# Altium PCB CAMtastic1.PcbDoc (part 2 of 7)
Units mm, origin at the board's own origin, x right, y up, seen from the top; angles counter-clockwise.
Board outline 150.22 x 135.24 mm, 5 copper layers (Top Layer, Layer 1, Mid-Layer 1, Layer 2, Bottom Layer), stack 0.461 mm thick; 0 components, 362 nets, 2885 pads, 0 vias.
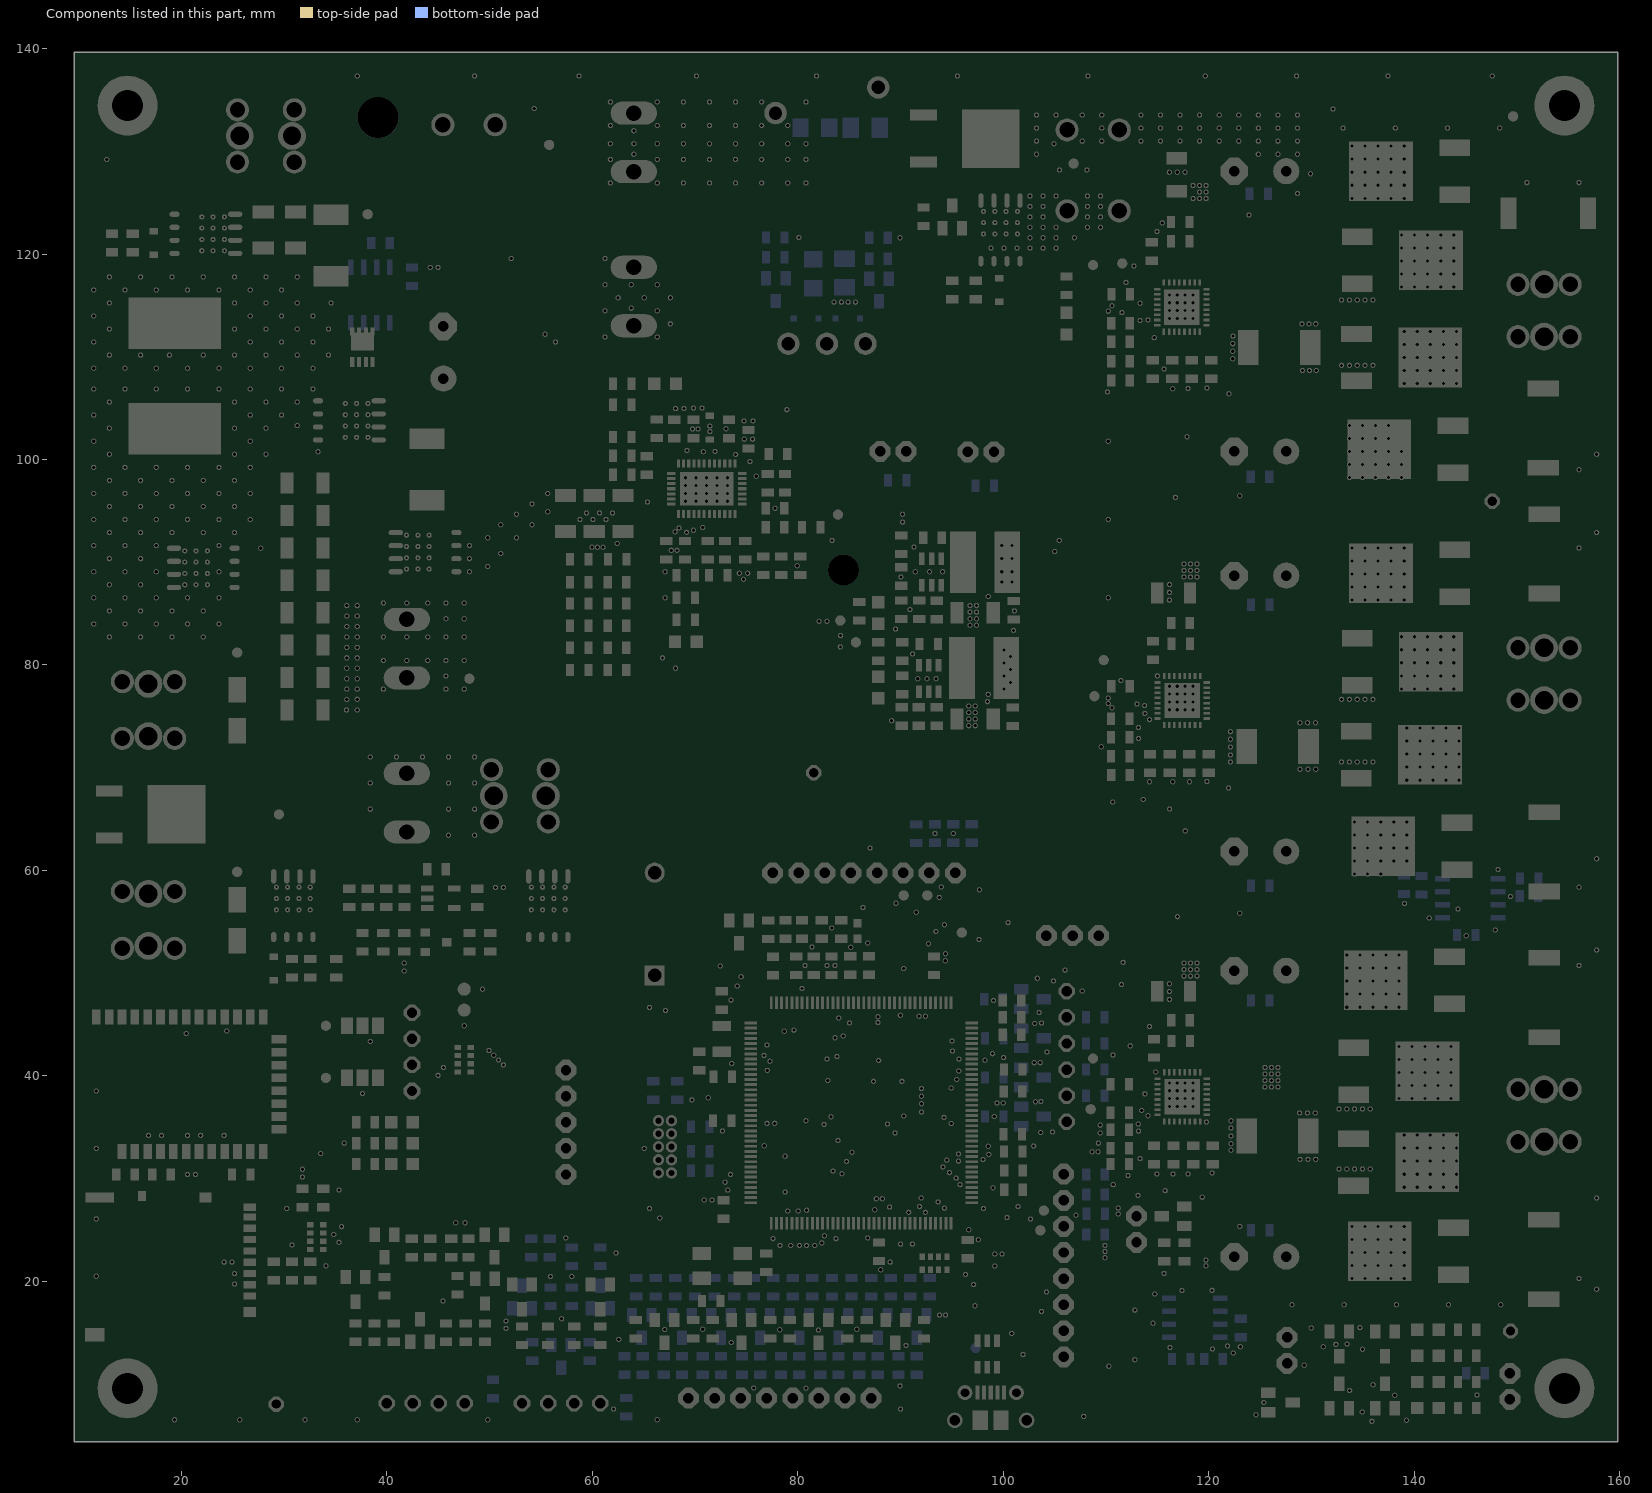
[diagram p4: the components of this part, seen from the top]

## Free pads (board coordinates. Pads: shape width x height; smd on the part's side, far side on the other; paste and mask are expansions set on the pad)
  round 0.508 hole 0.305 mask+0.61: 1(11.451,83.998) 1(11.451,86.538) 1(11.451,89.078) 1(11.451,91.618) 1(11.451,94.158) 1(11.451,96.698) 1(11.451,99.238) 1(11.451,101.778) 1(11.451,104.318) 1(11.451,106.858) 1(11.451,108.89) 1(11.451,111.43) 1(11.451,113.97) 1(11.451,116.51) 1(11.705,20.498) 1(11.705,26.086) 1(11.705,32.944) 1(11.705,38.532) 1(12.975,82.728) 1(12.975,85.268) 1(12.975,87.808) 1(12.975,90.348) 1(12.975,92.888) 1(12.975,95.428) 1(12.975,97.968) 1(12.975,100.508) 1(12.975,103.048) 1(12.975,105.588) 1(12.975,110.16) 1(12.975,112.7) 1(12.975,115.24) 1(12.975,117.78) 1(14.499,83.998) 1(14.499,86.538) 1(14.499,89.078) 1(14.499,91.618) 1(14.499,94.158) 1(14.499,96.698) 1(14.499,99.238) 1(14.499,106.858) 1(14.499,108.89) 1(14.499,116.51) 1(16.023,82.728) 1(16.023,85.268) 1(16.023,87.808) 1(16.023,90.348) 1(16.023,92.888) 1(16.023,95.428) 1(16.023,97.968) 1(16.023,110.16) 1(16.023,117.78) 1(16.785,34.214) 1(17.547,83.998) 1(17.547,86.538) 1(17.547,89.078) 1(17.547,91.618) 1(17.547,94.158) 1(17.547,96.698) 1(17.547,99.238) 1(17.547,106.858) 1(17.547,108.89) 1(17.547,116.51) 1(18.055,34.214) 1(18.817,110.16) 1(19.071,82.728) 1(19.071,85.268) 1(19.071,92.888) 1(19.071,95.428) 1(19.071,97.968) 1(19.071,117.78) 1(19.325,6.528) 1(20.455,44.12) 1(20.595,30.404) 1(20.595,34.214) 1(20.595,83.998) 1(20.595,86.538) 1(20.595,94.158) 1(20.595,96.698) 1(20.595,99.238) 1(20.595,106.858) 1(20.595,108.89) 1(20.595,116.51) 1(21.357,30.404) 1(21.865,34.214) 1(22.119,82.728) 1(22.119,85.268) 1(22.119,92.888) 1(22.119,95.428) 1(22.119,97.968) 1(22.119,110.16) 1(22.119,117.78) 1(23.643,83.998) 1(23.643,86.538) 1(23.643,89.078) 1(23.643,91.618) 1(23.643,94.158) 1(23.643,96.698) 1(23.643,99.238) 1(23.643,106.858) 1(23.643,108.89) 1(23.643,116.51) 1(24.151,21.868) 1(24.151,34.214) 1(24.405,44.374) 1(24.913,21.868) 1(25.167,19.736) 1(25.167,20.752) 1(25.167,92.888) 1(25.167,95.428) 1(25.167,97.968) 1(25.167,100.508) 1(25.167,103.048) 1(25.167,105.588) 1(25.167,110.16) 1(25.167,112.7) 1(25.167,115.24) 1(25.167,117.78) 1(25.675,6.528) 1(26.691,94.158) 1(26.691,96.698) 1(26.691,99.238) 1(26.691,101.778) 1(26.691,104.318) 1(26.691,106.858) 1(26.691,108.89) 1(26.691,111.43) 1(26.691,113.97) 1(26.691,116.51) 1(27.707,91.364) 1(28.215,100.508) 1(28.215,103.048) 1(28.215,105.588) 1(28.215,110.16) 1(28.215,112.7) 1(28.215,115.24) 1(28.215,117.78) 1(29.739,104.318) 1(29.739,106.858) 1(29.739,108.89) 1(29.739,111.43) 1(29.739,113.97) 1(29.739,116.51) 1(30.247,27.102) 1(30.755,23.546) 1(31.263,103.302) 1(31.263,105.588) 1(31.263,110.16) 1(31.263,112.7) 1(31.263,115.24) 1(31.263,117.78) 1(31.771,30.15) 1(31.771,30.912) 1(32.025,6.528) 1(32.787,106.858) 1(32.787,108.89) 1(32.787,111.43) 1(32.787,113.97) 1(33.295,100.762) 1(33.549,32.436) 1(34.057,21.514) 1(34.311,110.16) 1(34.311,112.7) 1(34.565,115.24) 1(34.819,24.562) 1(35.327,23.8) 1(35.327,28.88) 1(35.581,25.324) 1(35.835,33.452) 1(37.105,6.528) 1(37.105,137.338) 1(37.613,38.278) 1(38.375,43.358) 1(38.375,65.964) 1(38.375,68.504) 1(38.375,71.044) 1(39.645,77.648) 1(39.645,80.442) 1(39.645,82.728) 1(39.645,86.03) 1(40.915,71.044) 1(41.931,80.442) 1(41.931,82.728) 1(41.931,86.03) 1(43.455,71.044) 1(43.963,80.442) 1(43.963,82.728) 1(43.963,86.03) 1(44.217,118.702) 1(44.979,40.056) 1(44.979,118.702) 1(45.445,18.085) 1(45.487,40.818) 1(45.741,77.648) 1(45.741,78.918) 1(45.741,80.442) 1(45.741,82.728) 1(45.741,84.506) 1(45.741,86.03) 1(45.995,63.424) 1(45.995,65.964) 1(45.995,68.504) 1(45.995,71.044) 1(46.689,25.705) 1(47.519,44.882) 1(47.519,77.648) 1(47.519,80.442) 1(47.519,82.728) 1(47.519,84.506) 1(47.519,86.03) 1(47.604,25.705) 1(48.027,89.078) 1(48.027,90.348) 1(48.027,91.618) 1(48.535,63.424) 1(48.535,65.964) 1(48.535,68.504) 1(48.535,71.044) 1(48.535,137.338) 1(49.297,48.438) 1(49.805,6.528) 1(49.805,89.586) 1(49.805,92.38) 1(49.928,42.473) 1(50.395,42.006) 1(50.861,41.539) 1(51.075,90.856) 1(51.075,93.65) 1(51.329,41.072) 1(51.583,15.418) 1(51.591,16.129) 1(52.599,92.38) 1(52.599,94.666) 1(54.123,93.65) 1(54.123,95.682) 1(54.335,134.163) 1(55.393,112.192) 1(55.647,94.92) 1(55.647,96.698) 1(55.909,20.472) 1(56.409,111.43) 1(57.002,16.358) 1(57.408,24.232) 1(57.992,20.472) 1(58.695,137.338) 1(58.78,94.158) 1(59.415,94.793) 1(59.948,91.465) 1(60.05,94.158) 1(60.481,91.465) 1(60.685,94.793) 1(61.04,91.465) 1(61.235,111.938) 1(61.235,114.478) 1(61.235,117.018) 1(61.235,119.558) 1(61.32,94.158) 1(61.743,126.924) 1(61.743,129.21) 1(61.743,130.734) 1(61.743,132.512) 1(61.743,134.798) 1(61.955,94.793) 1(62.056,7.569) 1(62.31,22.758) 1(62.412,91.821) 1(62.505,115.748) 1(62.564,14.351) 1(63.775,114.732) 1(63.775,117.018) 1(64.029,129.718) 1(64.029,130.734) 1(64.029,132.004) 1(65.045,32.944) 1(65.045,115.748) 1(65.358,95.86) 1(65.553,27.102) 1(65.553,46.66) 1(66.315,6.528) 1(66.315,111.938) 1(66.315,114.478) 1(66.315,117.018) 1(66.315,126.924) 1(66.315,129.21) 1(66.315,130.734) 1(66.315,132.512) 1(66.315,134.798) 1(66.552,26.162) 1(66.823,80.696) 1(67.035,15.316) 1(67.077,86.538) 1(67.077,89.078) 1(67.111,46.355) 1(67.585,113.208) 1(67.585,115.748) 1(67.67,91.161) 1(68.051,92.964) 1(68.093,79.68) 1(68.101,104.953) 1(68.228,91.161) 1(68.432,93.345) 1(68.855,126.924) 1(68.855,129.21) 1(68.855,130.734) 1(68.855,132.512) 1(68.855,134.798) 1(68.914,104.978) 1(69.067,95.936) 1(69.067,96.698) 1(69.067,97.46) 1(69.067,98.222) 1(69.168,92.913) 1(69.194,100.889) 1(69.676,37.668) 1(69.752,102.972) 1(69.829,93.116) 1(69.829,105.004) 1(70.083,95.936) 1(70.083,96.698) 1(70.083,97.46) 1(70.083,98.222) 1(70.125,137.338) 1(70.286,102.972) 1(70.667,105.004) 1(70.743,15.342) 1(70.743,93.37) 1(70.794,100.762) 1(70.887,27.915) 1(71.099,95.936) 1(71.099,96.698) 1(71.099,97.46) 1(71.099,98.222) 1(71.276,37.871) 1(71.395,126.924) 1(71.395,129.21) 1(71.395,130.734) 1(71.395,132.512) 1(71.395,134.798) 1(71.429,102.718) 1(71.429,103.251) 1(71.645,27.915) 1(71.937,100.787) 1(72.115,95.936) 1(72.115,96.698) 1(72.115,97.46) 1(72.115,98.222) 1(72.445,50.698) 1(72.648,34.646) 1(72.919,29.642) 1(73.004,102.997) 1(73.131,95.936) 1(73.131,96.698) 1(73.131,97.46) 1(73.131,98.222) 1(73.173,28.88) 1(73.427,30.404) 1(73.486,47.371) 1(73.512,14.046) 1(73.562,41.199) 1(73.935,126.924) 1(73.935,129.21) 1(73.935,130.734) 1(73.935,132.512) 1(73.935,134.798) 1(73.943,100.482) 1(74.096,48.743) 1(74.299,88.925) 1(74.477,49.657) 1(74.705,88.341) 1(74.756,103.759) 1(74.782,101.981) 1(75.112,88.925) 1(75.34,99.797) 1(75.594,101.981) 1(75.62,103.759) 1(75.696,9.627) 1(75.95,98.374) 1(76.475,126.924) 1(76.475,129.21) 1(76.475,130.734) 1(76.475,132.512) 1(76.475,134.798) 1(76.712,41.986) 1(76.729,33.198) 1(76.991,43.002) 1(77.004,35.382) 1(77.017,40.538) 1(77.271,41.427) 1(77.576,24.155) 1(77.745,35.382) 1(77.779,95.25) 1(78.236,15.291) 1(78.261,23.495) 1(78.668,44.348) 1(78.761,28.694) 1(78.761,32.182) 1(78.922,104.851) 1(79.015,26.848) 1(79.015,126.924) 1(79.015,129.21) 1(79.015,130.734) 1(79.015,132.512) 1(79.303,23.495) 1(79.608,44.45) 1(79.938,89.662) 1(80.031,26.848) 1(80.09,121.615) 1(80.141,23.495) 1(80.395,48.514) 1(80.7,50.749) 1(80.776,9.601) 1(80.776,35.636) 1(80.793,126.924) 1(80.793,129.21) 1(80.793,130.734) 1(80.793,134.798) 1(80.852,23.495) 1(80.852,26.924) 1(81.36,52.553) 1(81.64,23.495) 1(81.809,137.338) 1(81.995,15.265) 1(82.063,84.252) 1(82.325,23.749) 1(82.554,35.281) 1(82.579,24.435) 1(82.825,84.252) 1(82.833,41.656) 1(82.833,50.749) 1(82.91,39.548) 1(83.214,36.017) 1(83.291,54.407) 1(83.333,92.126) 1(83.418,30.734) 1(83.519,115.316) 1(83.595,50.749) 1(83.621,43.713) 1(83.697,24.155) 1(83.799,41.885) 1(83.905,33.727) 1(83.976,45.644) 1(84.129,81.763) 1(84.154,82.855) 1(84.23,115.316) 1(84.281,30.48) 1(84.408,43.891) 1(84.738,31.674) 1(84.891,115.316) 1(85.018,45.161) 1(85.145,52.527) 1(85.272,32.563) 1(85.602,115.316) 1(85.729,15.342) 1(86.339,56.388) 1(86.796,24.232) 1(86.796,52.934) 1(87.024,62.179) 1(87.355,39.472) 1(87.482,26.975) 1(87.634,28.042) 1(87.786,45.199) 1(87.786,45.758) 1(87.863,41.504) 1(88.066,21.133) 1(88.218,28.042) 1(88.726,35.306) 1(88.929,27.229) 1(88.98,21.869) 1(89.128,74.574) 1(89.463,34.442) 1(89.514,83.49) 1(89.539,56.807) 1(89.937,121.59) 1(89.945,9.83) 1(89.971,45.898) 1(89.996,7.569) 1(89.996,23.622) 1(90.022,88.57) 1(90.123,39.472) 1(90.191,93.904) 1(90.191,94.666) 1(90.301,36.093) 1(90.301,50.444) 1(90.53,13.767) 1(90.784,26.721) 1(90.911,85.395) 1(91.139,23.622) 1(91.165,81.077) 1(91.292,91.491) 1(91.419,89.078) 1(91.52,55.931) 1(91.673,78.664) 1(91.8,45.809) 1(91.85,27.28) 1(92.003,28.118) 1(92.028,36.474) 1(92.028,37.287) 1(92.028,38.024) 1(92.028,38.76) 1(92.409,26.721) 1(92.409,45.809) 1(92.562,78.664) 1(92.714,52.857) 1(92.816,89.078) 1(93.349,63.602) 1(93.425,54.051) 1(93.451,78.664) 1(93.654,27.737) 1(93.755,57.379) 1(93.794,16.713) 1(93.959,58.395) 1(94.086,89.078) 1(94.111,31.14) 1(94.213,35.966) 1(94.263,27.127) 1(94.263,54.712) 1(94.34,51.206) 1(94.365,51.892) 1(94.378,16.713) 1(94.492,31.801) 1(94.746,30.582) 1(94.924,35.357) 1(94.924,38.811) 1(95,43.409) 1(95.051,42.418) 1(95.127,63.602) 1(95.406,30.048) 1(95.457,39.649) 1(95.525,137.338) 1(95.635,31.699) 1(95.635,32.41) 1(95.66,40.488) 1(95.686,41.631) 1(95.787,29.413) 1(96.321,20.676) 1(96.626,25.019) 1(96.626,74.092) 1(96.626,74.727) 1(96.626,75.362) 1(96.626,75.997) 1(96.753,83.871) 1(96.753,84.506) 1(96.753,85.141) 1(96.753,85.776) 1(97.108,19.685) 1(97.235,17.628) 1(97.261,74.092) 1(97.261,74.727) 1(97.261,75.362) 1(97.261,75.997) 1(97.388,83.871) 1(97.388,84.506) 1(97.388,85.141) 1(97.388,85.776) 1(97.565,24.054) 1(97.616,53.289) 1(97.667,58.115) 1(98.023,31.852) 1(98.065,27.102) 1(98.2,41.529) 1(98.454,76.429) 1(98.531,33.147) 1(98.531,77.14) 1(98.531,86.665) 1(98.581,32.36) 1(98.785,120.574) 1(98.937,42.164) 1(98.988,29.108) 1(99.039,47.346) 1(99.115,36.043) 1(99.166,21.488) 1(99.166,22.657) 1(99.382,37.363) 1(99.843,88.062) 1(99.843,89.078) 1(99.843,90.348) 1(99.843,91.618) 1(99.877,22.657) 1(99.991,37.363) 1(100.029,41.783) 1(100.055,77.648) 1(100.055,78.918) 1(100.055,80.188) 1(100.055,81.458) 1(100.055,120.574) 1(100.359,26.213) 1(100.461,54.915) 1(100.69,78.283) 1(100.69,79.553) 1(100.69,80.823) 1(100.817,14.935) 1(100.859,88.062) 1(100.859,89.078) 1(100.859,90.348) 1(100.859,91.618) 1(100.994,83.363) 1(101.071,85.268) 1(101.325,120.574) 1(101.426,27.28) 1(101.909,12.878) 1(102.595,120.574) 1(102.595,121.59) 1(102.595,122.606) 1(102.595,123.622) 1(102.595,124.638) 1(102.595,125.654) 1(102.645,26.06) 1(102.95,33.172) 1(103.001,41.288) 1(103.052,45.098) 1(103.128,37.478) 1(103.23,129.718) 1(103.23,130.988) 1(103.23,132.258) 1(103.23,133.528) 1(103.306,49.505) 1(103.484,46.177) 1(103.585,41.288) 1(103.636,34.493) 1(103.653,37.516) 1(103.711,45.14) 1(103.712,17.069) 1(103.865,120.574) 1(103.865,121.59) 1(103.865,122.606) 1(103.865,123.622) 1(103.865,124.638) 1(103.865,125.654) 1(104.195,18.974) 1(104.246,42.316) 1(104.779,34.544) 1(104.881,49.251) 1(104.923,130.734) 1(105.008,91.034) 1(105.135,120.574) 1(105.135,121.59) 1(105.135,122.606) 1(105.135,125.654) 1(105.135,133.528) 1(105.439,92.126) 1(105.465,128.194) 1(105.998,50.292) 1(106.913,121.59) 1(107.065,26.441) 1(107.675,48.26) 1(107.675,130.988) 1(107.675,133.528) 1(107.827,6.858) 1(108.132,128.194) 1(108.183,122.606) 1(108.183,123.622) 1(108.183,124.638) 1(108.183,125.654) 1(108.225,137.338) 1(108.64,32.614) 1(109.224,32.614) 1(109.249,33.452) 1(109.427,34.442) 1(109.427,35.204) 1(109.453,122.606) 1(109.453,123.622) 1(109.453,124.638) 1(109.453,125.654) 1(109.529,72.034) 1(109.58,130.988) 1(109.58,132.258) 1(109.58,133.528) 1(109.884,22.301) 1(109.884,22.911) 1(109.884,23.495) 1(110.138,106.578) 1(110.215,76.238) 1(110.215,76.772) 1(110.215,86.538) 1(110.215,94.158) 1(110.215,101.778) 1(110.215,114.44) 1(110.265,11.735) 1(110.57,75.832) 1(110.57,114.973) 1(110.646,66.65) 1(110.672,42.037) 1(110.697,29.413) 1(111.18,26.568) 1(111.18,27.127) 1(111.434,78.486) 1(111.485,48.895) 1(111.535,114.3) 1(111.662,51.054) 1(111.942,117.246) 1(112.145,30.302) 1(112.348,42.926) 1(112.704,118.834) 1(112.797,12.37) 1(112.797,17.196) 1(113.009,76.2) 1(113.11,28.372) 1(113.132,35.302) 1(113.161,34.62) 1(113.161,72.847) 1(113.161,73.914) 1(113.313,31.953) 1(113.313,113.538) 1(113.313,115.214) 1(113.39,130.988) 1(113.39,132.258) 1(113.39,133.528) 1(113.466,36.627) 1(113.618,66.904) 1(113.745,76.048) 1(113.771,38.252) 1(113.771,75.286) 1(114.075,36.119) 1(114.075,113.589) 1(114.228,44.806) 1(114.228,68.631) 1(114.228,74.676) 1(114.685,111.862) 1(114.736,18.771) 1(114.837,40.386) 1(114.939,30.455) 1(114.964,122.199) 1(114.99,78.943) 1(115.295,130.988) 1(115.295,132.258) 1(115.295,133.528) 1(115.472,123.038) 1(115.65,20.777) 1(115.65,108.814) 1(115.752,28.829) 1(116.158,37.033) 1(116.158,37.795) 1(116.158,38.557) 1(116.158,39.319) 1(116.158,47.447) 1(116.158,48.209) 1(116.158,48.971) 1(116.158,75.641) 1(116.158,76.403) 1(116.158,77.165) 1(116.158,77.927) 1(116.158,86.309) 1(116.158,87.071) 1(116.158,87.833) 1(116.158,113.741) 1(116.158,114.503) 1(116.158,115.265) 1(116.158,116.027) 1(116.158,127.965) 1(116.184,65.989) 1(116.209,13.564) 1(116.488,68.631) 1(116.488,106.883) 1(116.514,30.455) 1(116.742,96.317) 1(116.92,37.033) 1(116.92,37.795) 1(116.92,38.557) 1(116.92,39.319) 1(116.92,75.641) 1(116.92,76.403) 1(116.92,77.165) 1(116.92,77.927) 1(116.92,113.741) 1(116.92,114.503) 1(116.92,115.265) 1(116.92,116.027) 1(116.92,127.965) 1(116.946,55.499) 1(117.2,130.988) 1(117.2,132.258) 1(117.2,133.528) 1(117.377,19.101) 1(117.581,49.708) 1(117.581,50.343) 1(117.581,50.978) 1(117.581,88.57) 1(117.581,89.205) 1(117.581,89.84) 1(117.682,37.033) 1(117.682,37.795) 1(117.682,38.557) 1(117.682,39.319) 1(117.682,75.641) 1(117.682,76.403) 1(117.682,77.165) 1(117.682,77.927) 1(117.682,113.741) 1(117.682,114.503) 1(117.682,115.265) 1(117.682,116.027) 1(117.682,127.965) 1(117.708,63.856) 1(117.885,102.21) 1(117.987,30.455) 1(117.987,106.909) 1(118.114,68.631) 1(118.216,49.708) 1(118.216,50.343) 1(118.216,50.978) 1(118.216,88.57) 1(118.216,89.205) 1(118.216,89.84) 1(118.444,37.033) 1(118.444,37.795) 1(118.444,38.557) 1(118.444,39.319) 1(118.444,75.641) 1(118.444,76.403) 1(118.444,77.165) 1(118.444,77.927) 1(118.444,113.741) 1(118.444,114.503) 1(118.444,115.265) 1(118.444,116.027) 1(118.47,125.4) 1(118.47,126.67) 1(118.851,49.708) 1(118.851,50.343) 1(118.851,50.978) 1(118.851,88.57) 1(118.851,89.205) 1(118.851,89.84) 1(119.105,125.4) 1(119.105,126.035) 1(119.105,126.67) 1(119.105,130.988) 1(119.105,132.258) 1(119.105,133.528) 1(119.359,28.194) 1(119.655,137.338) 1(119.714,21.514) 1(119.714,22.073) 1(119.74,125.4) 1(119.74,126.035) 1(119.74,126.67) 1(119.765,35.509) 1(119.816,68.656) 1(119.816,106.959) 1(120.324,19.126) 1(120.324,30.556) 1(120.349,13.411) 1(121.01,130.988) 1(121.01,132.258) 1(121.01,133.528) 1(121.822,13.716) 1(121.924,68.021) 1(121.949,106.401) 1(122.102,70.561) 1(122.102,71.247) 1(122.102,72.009) 1(122.102,72.771) 1(122.102,73.508) 1(122.153,32.766) 1(122.153,33.401) 1(122.153,34.163) 1(122.153,34.925) 1(122.153,35.636) 1(122.328,109.804) 1(122.328,110.541) 1(122.328,111.277) 1(122.353,112.014) 1(122.381,13.03) 1(122.915,130.988) 1(122.915,132.258) 1(122.915,133.528) 1(123.016,25.349) 1(123.016,55.829) 1(123.016,96.469) 1(123.067,13.64) 1(123.905,123.8) 1(124.591,7.01) 1(124.82,129.718) 1(124.82,130.988) 1(124.82,132.258) 1(124.82,133.528) 1(125.353,8.204) 1(125.455,38.913) 1(125.455,39.548) 1(125.455,40.183) 1(125.455,40.818) 1(126.09,38.913) 1(126.09,39.548) 1(126.09,40.183) 1(126.09,40.818) 1(126.725,38.913) 1(126.725,39.548) 1(126.725,40.183) 1(126.725,40.818) 1(126.725,129.718) 1(126.725,130.988) 1(126.725,132.258) 1(126.725,133.528) 1(128.096,17.729) 1(128.545,137.338) 1(128.63,125.908) 1(128.63,129.718) 1(128.63,130.988) 1(128.63,132.258) 1(128.63,133.528) 1(128.833,36.398) 1(128.858,74.371) 1(128.884,31.877) 1(128.884,69.85) 1(129.061,113.208) 1(129.112,108.661) 1(129.29,11.836) 1(129.595,36.398) 1(129.62,74.371) 1(129.646,31.877) 1(129.646,69.85) 1(129.747,113.208) 1(129.798,108.661) 1(129.9,127.813) 1(129.976,15.469) 1(130.357,36.398) 1(130.382,74.371) 1(130.408,31.877) 1(130.408,69.85) 1(130.408,113.208) 1(130.458,108.661) 1(131.144,13.64) 1(132.084,134.112) 1(132.363,13.868) 1(132.668,30.937) 1(132.668,36.779) 1(132.922,70.561) 1(132.922,76.657) 1(132.922,109.169) 1(132.922,115.519) 1(133.075,132.258) 1(133.176,17.729) 1(133.43,30.937) 1(133.43,36.779) 1(133.43,46.685) 1(133.43,47.955) 1(133.43,49.225) 1(133.43,50.495) 1(133.43,51.765) 1(133.456,13.894) 1(133.684,70.561) 1(133.684,76.657) 1(133.684,98.247) 1(133.684,99.517) 1(133.684,100.787) 1(133.684,102.057) 1(133.684,103.327) 1(133.684,109.169) 1(133.684,115.519) 1(133.71,9.373) 1(133.938,20.269) 1(133.938,21.539) 1(133.938,22.809) 1(133.938,24.079) 1(133.938,25.349) 1(133.938,86.309) 1(133.938,87.579) 1(133.938,88.849) 1(133.938,90.119) 1(133.938,91.389) 1(133.938,125.425) 1(133.938,126.695) 1(133.938,127.965) 1(133.938,129.235) 1(133.938,130.505) 1(134.192,30.937) 1(134.192,36.779) 1(134.192,59.639) 1(134.192,60.909) 1(134.192,62.179) 1(134.192,63.449) 1(134.192,64.719) 1(134.446,70.561) 1(134.446,76.657) 1(134.446,109.169) 1(134.446,115.519) 1(134.7,15.494) 1(134.7,46.685) 1(134.7,47.955) 1(134.7,49.225) 1(134.7,50.495) 1(134.7,51.765) 1(134.929,7.29) 1(134.954,13.386) 1(134.954,30.937) 1(134.954,36.779) 1(134.954,98.247) 1(134.954,99.517) 1(134.954,100.787) 1(134.954,102.057) 1(134.954,103.327) 1(135.208,20.269) 1(135.208,21.539) 1(135.208,22.809) 1(135.208,24.079) 1(135.208,25.349) 1(135.208,70.561) 1(135.208,76.657) 1(135.208,86.309) 1(135.208,87.579) 1(135.208,88.849) 1(135.208,90.119) 1(135.208,91.389) 1(135.208,109.169) 1(135.208,115.519) 1(135.208,125.425) 1(135.208,126.695) 1(135.208,127.965) 1(135.208,129.235) 1(135.208,130.505) 1(135.462,59.639) 1(135.462,60.909) 1(135.462,62.179) 1(135.462,63.449) 1(135.462,64.719) 1(135.716,30.937) 1(135.716,36.779) 1(135.869,6.375) 1(135.97,46.685) 1(135.97,47.955) 1(135.97,49.225) 1(135.97,50.495) 1(135.97,51.765) 1(135.97,70.561) 1(135.97,76.657) 1(135.97,109.169) 1(135.97,115.519) 1(135.996,9.931) 1(136.224,98.247) 1(136.224,99.517) 1(136.224,100.787) 1(136.224,102.057) 1(136.224,103.327) 1(136.478,20.269) 1(136.478,21.539) 1(136.478,22.809) 1(136.478,24.079) 1(136.478,25.349) 1(136.478,86.309) 1(136.478,87.579) 1(136.478,88.849) 1(136.478,90.119) 1(136.478,91.389) 1(136.478,125.425) 1(136.478,126.695) 1(136.478,127.965) 1(136.478,129.235) 1(136.478,130.505) 1(136.732,59.639) 1(136.732,60.909) 1(136.732,62.179) 1(136.732,63.449) 1(136.732,64.719) 1(137.24,46.685) 1(137.24,47.955) 1(137.24,49.225) 1(137.24,50.495) 1(137.24,51.765) 1(137.435,137.338) 1(137.494,98.247) 1(137.494,99.517) 1(137.494,100.787) 1(137.494,102.057) 1(137.494,103.327) 1(137.748,20.269) 1(137.748,21.539) 1(137.748,22.809) 1(137.748,24.079) 1(137.748,25.349) 1(137.748,86.309) 1(137.748,87.579) 1(137.748,88.849) 1(137.748,90.119) 1(137.748,91.389) 1(137.748,125.425) 1(137.748,126.695) 1(137.748,127.965) 1(137.748,129.235) 1(137.748,130.505) 1(138.002,60.909) 1(138.002,62.179) 1(138.002,63.449) 1(138.002,64.719) 1(138.104,8.915) 1(138.155,132.258) 1(138.256,17.729) 1(138.51,37.795) 1(138.51,39.065) 1(138.51,40.335) 1(138.51,41.605) 1(138.51,42.875) 1(138.51,46.685) 1(138.51,47.955) 1(138.51,49.225) 1(138.51,50.495) 1(138.51,51.765) 1(138.764,77.673) 1(138.764,78.943) 1(138.764,80.213) 1(138.764,81.483) 1(138.764,82.753) 1(138.764,98.247) 1(138.764,99.517) 1(138.764,100.787) 1(138.764,116.789) 1(138.764,118.059) 1(138.764,119.329) 1(138.764,120.599) 1(138.764,121.869) 1(139.018,20.269) 1(139.018,21.539) 1(139.018,22.809) 1(139.018,24.079) 1(139.018,25.349) 1(139.018,29.159) 1(139.018,30.429) 1(139.018,31.699) 1(139.018,32.969) 1(139.018,34.239) 1(139.018,86.309) 1(139.018,87.579) 1(139.018,88.849) 1(139.018,90.119) 1(139.018,91.389) 1(139.018,107.391) 1(139.018,108.661) 1(139.018,109.931) 1(139.018,111.201) 1(139.018,112.471) 1(139.018,125.425) 1(139.018,126.695) 1(139.018,127.965) 1(139.018,129.235) 1(139.018,130.505) 1(139.046,56.769) 1(139.247,6.477) 1(139.272,60.909) 1(139.272,62.179) 1(139.272,63.449) 1(139.272,64.719) 1(139.272,68.783) 1(139.272,70.053) 1(139.272,71.323) 1(139.272,72.593) 1(139.272,73.863) 1(139.78,37.795) 1(139.78,39.065) 1(139.78,40.335) 1(139.78,41.605) 1(139.78,42.875) 1(140.034,77.673) 1(140.034,78.943) 1(140.034,80.213) 1(140.034,81.483) 1(140.034,82.753) 1(140.034,116.789) 1(140.034,118.059) 1(140.034,119.329) 1(140.034,120.599) 1(140.034,121.869) 1(140.288,29.159) 1(140.288,30.429) 1(140.288,31.699) 1(140.288,32.969) 1(140.288,34.239) 1(140.288,107.391) 1(140.288,108.661) 1(140.288,109.931) 1(140.288,111.201) 1(140.288,112.471) 1(140.542,68.783) 1(140.542,70.053) 1(140.542,71.323) 1(140.542,72.593) 1(140.542,73.863) 1(141.05,37.795) 1(141.05,39.065) 1(141.05,40.335) 1(141.05,41.605) 1(141.05,42.875) 1(141.304,77.673) 1(141.304,78.943) 1(141.304,80.213) 1(141.304,81.483) 1(141.304,82.753) 1(141.304,116.789) 1(141.304,118.059) 1(141.304,119.329) 1(141.304,120.599) 1(141.304,121.869) 1(141.459,55.372) 1(141.558,29.159) 1(141.558,30.429) 1(141.558,31.699) 1(141.558,32.969) 1(141.558,34.239) 1(141.558,107.391) 1(141.558,108.661) 1(141.558,111.201) 1(141.558,112.471) 1(141.812,68.783) 1(141.812,70.053) 1(141.812,71.323) 1(141.812,72.593) 1(141.812,73.863) 1(142.32,37.795) 1(142.32,39.065) 1(142.32,40.335) 1(142.32,41.605) 1(142.32,42.875) 1(142.574,77.673) 1(142.574,78.943) 1(142.574,80.213) 1(142.574,81.483) 1(142.574,82.753) 1(142.574,116.789) 1(142.574,118.059) 1(142.574,119.329) 1(142.574,120.599) 1(142.574,121.869) 1(142.828,29.159) 1(142.828,30.429) 1(142.828,31.699) 1(142.828,32.969) 1(142.828,34.239) 1(142.828,107.391) 1(142.828,108.661) 1(142.828,109.931) 1(142.828,111.201) 1(142.828,112.471) 1(143.082,68.783) 1(143.082,70.053) 1(143.082,71.323) 1(143.082,72.593) 1(143.082,73.863) 1(143.235,132.258) 1(143.336,17.729) 1(143.59,37.795) 1(143.59,39.065) 1(143.59,40.335) 1(143.59,41.605) 1(143.59,42.875) 1(143.844,77.673) 1(143.844,78.943) 1(143.844,80.213) 1(143.844,81.483) 1(143.844,82.753) 1(143.844,116.789) 1(143.844,118.059) 1(143.844,119.329) 1(143.844,120.599) 1(143.844,121.869) 1(144.098,29.159) 1(144.098,30.429) 1(144.098,31.699) 1(144.098,32.969) 1(144.098,34.239) 1(144.098,107.391) 1(144.098,108.661) 1(144.098,109.931) 1(144.098,111.201) 1(144.098,112.471) 1(144.251,56.236) 1(144.352,68.783) 1(144.352,70.053) 1(144.352,71.323) 1(144.352,72.593) 1(144.352,73.863) 1(145.063,53.645) 1(146.105,8.941) 1(147.595,137.338) 1(147.885,54.204) 1(148.162,60.096) 1(148.315,132.258) 1(148.416,17.729) 1(149.356,57.455) 1(150.956,126.949) 1(156.036,20.269) 1(156.036,50.749) 1(156.036,58.369) 1(156.036,91.389) 1(156.036,99.009) 1(156.036,126.949) 1(157.755,19.228) 1(157.755,28.118) 1(157.755,52.248) 1(157.755,61.138) 1(157.755,92.888) 1(157.755,100.508)
  rect 1.9x1.3 smd paste+0 mask+0.102: 1(11.542,14.818)
  rect 0.838x1.448 smd paste+0 mask+0.102: 1(11.692,45.738) 1(12.957,45.738) 1(14.206,32.631) 1(14.206,45.738) 1(15.456,32.631) 1(15.456,45.738) 1(16.706,32.631) 1(16.706,45.738) 1(17.956,32.631) 1(17.956,45.738) 1(19.205,32.631) 1(19.205,45.738) 1(20.455,32.631) 1(20.455,45.738) 1(21.705,32.631) 1(21.705,45.738) 1(22.954,32.631) 1(22.954,45.738) 1(24.204,32.631) 1(24.204,45.738) 1(25.454,32.631) 1(25.454,45.738) 1(26.703,32.631) 1(26.703,45.738) 1(27.953,32.631) 1(27.953,45.738)
  rect 2.8x1 smd paste+0 mask+0.102: 1(12.042,28.168)
  round 0.508 hole 0.305 mask+0.102: 1(12.721,129.21) 1(36.063,75.616) 1(36.089,76.632) 1(36.089,77.648) 1(36.089,78.664) 1(36.089,79.68) 1(36.089,80.696) 1(36.089,81.712) 1(36.089,82.728) 1(36.089,83.744) 1(36.089,84.76) 1(36.089,85.776) 1(37.105,75.616) 1(37.105,76.657) 1(37.105,77.648) 1(37.105,78.664) 1(37.105,79.68) 1(37.105,80.696) 1(37.105,81.712) 1(37.105,82.728) 1(37.105,83.744) 1(37.105,84.76) 1(37.105,85.776) 1(41.677,50.216) 1(41.677,50.978) 1(50.567,58.344) 1(51.329,58.344) 1(52.091,119.558) 1(114.575,15.926)
  rect 2.6x1.06 smd paste+0 mask+0.102: 1(12.975,63.17) 1(12.975,67.742) 1(92.223,128.956) 1(92.223,133.528)
  rect 1.2x0.8 smd paste+0 mask+0.102: 1(13.229,120.182) 1(13.229,121.982) 1(15.261,120.182) 1(15.261,121.982) 1(28.977,20.106) 1(28.977,21.906) 1(30.755,20.106) 1(30.755,21.906) 1(30.755,49.57) 1(30.755,51.37) 1(31.771,27.218) 1(31.771,29.018) 1(32.533,20.106) 1(32.533,21.906) 1(32.533,49.57) 1(32.533,51.37) 1(33.783,27.218) 1(33.783,29.018) 1(35.073,49.57) 1(35.073,51.37) 1(36.343,56.428) 1(36.343,58.228) 1(36.936,14.111) 1(36.936,15.911) 1(37.613,52.11) 1(37.613,53.91) 1(38.128,56.428) 1(38.128,58.228) 1(38.79,14.111) 1(38.79,15.911) 1(39.645,52.11) 1(39.645,53.91) 1(39.755,18.633) 1(39.755,20.433) 1(39.915,56.428) 1(39.915,58.228) 1(40.669,14.111) 1(40.669,15.911) 1(41.677,52.11) 1(41.677,53.91) 1(41.7,56.428) 1(41.7,58.228) 1(42.422,22.341) 1(42.422,24.141) 1(44.2,22.341) 1(44.2,24.141) 1(45.749,14.111) 1(45.749,15.911) 1(46.257,22.341) 1(46.257,24.141) 1(46.867,18.734) 1(46.867,20.534) 1(47.654,14.111) 1(47.654,15.911) 1(47.934,22.341) 1(47.934,24.141) 1(48.027,52.11) 1(48.027,53.91) 1(48.789,56.428) 1(48.789,58.228) 1(49.534,14.111) 1(49.534,15.911) 1(50.059,52.11) 1(50.059,53.91) 1(53.141,13.807) 1(53.141,15.607) 1(55.681,13.807) 1(55.681,15.607) 1(58.221,13.807) 1(58.221,15.607) 1(60.761,13.807) 1(60.761,15.607) 1(64.215,14.442) 1(64.215,16.242) 1(65.285,98.516) 1(65.285,100.316) 1(66.273,102.094) 1(66.273,103.894) 1(67.19,90.261) 1(67.19,92.061) 1(67.977,102.072) 1(67.977,103.872) 1(69.006,90.273) 1(69.006,92.073) 1(69.803,14.442) 1(69.803,16.242) 1(69.831,102.072) 1(69.831,103.872) 1(70.413,40.553) 1(70.413,42.353) 1(71.226,90.263) 1(71.226,92.063) 1(71.708,14.442) 1(71.708,16.242) 1(72.597,46.446) 1(72.597,48.246) 1(72.75,26.1) 1(72.75,27.9) 1(72.905,90.261) 1(72.905,92.061) 1(73.286,102.072) 1(73.286,103.872) 1(74.861,90.261) 1(74.861,92.061) 1(75.191,101.081) 1(75.191,102.881) 1(76.613,88.762) 1(76.613,90.562) 1(76.915,20.919) 1(76.915,22.719) 1(77.07,96.788) 1(77.07,98.588) 1(77.118,53.329) 1(77.118,55.129) 1(77.296,14.442) 1(77.296,16.242) 1(77.576,49.798) 1(77.576,51.598) 1(78.366,88.762) 1(78.366,90.562) 1(78.747,96.788) 1(78.747,98.588) 1(78.795,53.354) 1(78.795,55.154) 1(79.201,14.442) 1(79.201,16.242) 1(79.836,49.824) 1(79.836,51.624) 1(80.217,88.759) 1(80.217,90.559) 1(80.395,53.354) 1(80.395,55.154) 1(81.538,49.824) 1(81.538,51.624) 1(82.325,53.354) 1(82.325,55.154) 1(83.265,49.824) 1(83.265,51.624) 1(84.23,53.354) 1(84.23,55.154) 1(84.789,14.442) 1(84.789,16.242) 1(85.094,49.849) 1(85.094,51.649) 1(85.983,84.317) 1(85.983,86.117) 1(86.694,14.442) 1(86.694,16.242) 1(86.923,49.849) 1(86.923,51.649) 1(87.837,80.405) 1(87.837,82.205) 1(87.888,21.985) 1(87.888,23.785) 1(90.072,84.469) 1(90.072,86.269) 1(90.072,87.721) 1(90.072,89.521) 1(90.072,90.794) 1(90.072,92.594) 1(90.123,74.081) 1(90.123,75.881) 1(90.149,77.154) 1(90.149,78.954) 1(90.149,80.405) 1(90.149,82.205) 1(91.774,74.081) 1(91.774,75.881) 1(91.825,84.469) 1(91.825,86.269) 1(92.223,122.722) 1(92.223,124.522) 1(92.282,14.442) 1(92.282,16.242) 1(93.247,49.824) 1(93.247,51.624) 1(93.501,74.081) 1(93.501,75.881) 1(93.501,84.444) 1(93.501,86.244) 1(95.017,115.61) 1(95.017,117.41) 1(96.524,22.239) 1(96.524,24.039) 1(97.303,115.61) 1(97.303,117.41) 1(100.918,74.055) 1(100.918,75.855) 1(101.02,84.419) 1(101.02,86.219) 1(106.151,116.016) 1(106.151,117.816) 1(114.279,69.509) 1(114.279,71.309) 1(114.459,119.344) 1(114.459,121.144) 1(114.533,107.863) 1(114.533,109.663) 1(114.561,80.519) 1(114.561,82.319) 1(114.66,31.409) 1(114.66,33.209) 1(114.662,41.778) 1(114.662,43.578) 1(115.65,21.96) 1(115.65,23.76) 1(116.184,69.509) 1(116.184,71.309) 1(116.438,107.863) 1(116.438,109.663) 1(116.565,31.409) 1(116.565,33.209) 1(117.631,21.96) 1(117.631,23.76) 1(118.089,69.509) 1(118.089,71.309) 1(118.343,107.863) 1(118.343,109.663) 1(118.47,31.409) 1(118.47,33.209) 1(119.994,69.509) 1(119.994,71.309) 1(120.248,107.863) 1(120.248,109.663) 1(120.375,31.409) 1(120.375,33.209)
  rect 0.8x1.2 smd paste+0 mask+0.102: 1(13.637,30.404) 1(15.437,30.404) 1(17.155,30.404) 1(18.954,30.404) 1(24.922,30.404) 1(26.722,30.404) 1(37.001,31.42) 1(37.001,33.452) 1(37.001,35.484) 1(38.801,31.42) 1(38.801,33.452) 1(38.801,35.484) 1(43.927,60.122) 1(45.726,60.122) 1(57.81,79.509) 1(57.81,81.668) 1(57.81,83.827) 1(57.81,85.986) 1(57.81,88.044) 1(57.81,90.304) 1(59.609,79.509) 1(59.609,81.668) 1(59.609,83.827) 1(59.609,85.986) 1(59.609,88.044) 1(59.609,90.304) 1(61.493,79.509) 1(61.493,81.668) 1(61.493,83.827) 1(61.493,85.986) 1(61.493,88.044) 1(61.518,90.304) 1(61.997,98.527) 1(61.997,100.355) 1(61.997,102.184) 1(61.997,105.334) 1(61.997,107.366) 1(63.292,79.509) 1(63.292,81.668) 1(63.292,83.827) 1(63.292,85.986) 1(63.292,88.044) 1(63.318,90.304) 1(63.797,98.527) 1(63.797,100.355) 1(63.797,102.184) 1(63.797,105.334) 1(63.797,107.366) 1(68.192,84.416) 1(68.192,86.538) 1(68.192,88.722) 1(69.992,84.416) 1(69.992,86.538) 1(69.992,88.722) 1(70.656,18.085) 1(71.345,88.748) 1(71.748,35.636) 1(71.774,39.929) 1(72.456,18.085) 1(73.144,88.748) 1(73.548,35.636) 1(73.573,39.929) 1(76.879,93.396) 1(76.879,95.247) 1(77.158,100.536) 1(78.679,93.396) 1(78.679,95.247) 1(78.958,100.536) 1(80.401,93.396) 1(82.2,93.396) 1(91.84,82.042) 1(92.195,92.38) 1(93.639,82.042) 1(93.995,92.38) 1(99.942,44.018) 1(99.942,45.695) 1(99.942,47.346) 1(100.018,34.315) 1(100.044,38.481) 1(100.063,32.643) 1(100.069,40.615) 1(100.088,28.91) 1(100.088,30.789) 1(101.742,44.018) 1(101.742,45.695) 1(101.742,47.346) 1(101.818,34.315) 1(101.844,38.481) 1(101.863,32.643) 1(101.869,40.615) 1(101.888,28.91) 1(101.888,30.789) 1(110.43,31.42) 1(110.435,32.969) 1(110.435,34.773) 1(110.435,36.398) 1(110.435,39.198) 1(110.486,71.12) 1(110.486,72.974) 1(110.486,74.752) 1(110.506,69.291) 1(110.511,77.914) 1(110.511,107.696) 1(110.511,109.55) 1(110.511,111.455) 1(110.511,113.259) 1(110.536,116.078) 1(112.23,31.42) 1(112.235,32.969) 1(112.235,34.773) 1(112.235,36.398) 1(112.235,39.198) 1(112.286,71.12) 1(112.286,72.974) 1(112.286,74.752) 1(112.306,69.291) 1(112.311,77.914) 1(112.311,107.696) 1(112.311,109.55) 1(112.311,111.455) 1(112.311,113.259) 1(112.336,116.078) 1(116.328,121.234) 1(116.328,123.114) 1(116.353,45.421) 1(116.353,84.086) 1(116.378,43.389) 1(116.378,82.08) 1(118.128,121.234) 1(118.128,123.114) 1(118.153,45.421) 1(118.153,84.086) 1(118.178,43.389) 1(118.178,82.08) 1(144.242,7.671) 1(144.242,10.211) 1(144.242,12.751) 1(144.242,15.291) 1(146.042,7.671) 1(146.042,10.211) 1(146.042,12.751) 1(146.042,15.291)
  round 2.25 hole 1.5 mask+0.102: 1(14.245,52.421) 1(14.245,57.951) 1(14.245,72.851) 1(14.245,78.381) 1(19.325,52.421) 1(19.325,57.951) 1(19.325,72.851) 1(19.325,78.381) 1(25.45,128.956) 1(25.45,134.036) 1(30.98,128.956) 1(30.98,134.036) 1(45.445,132.588) 1(50.17,64.718) 1(50.17,69.798) 1(50.525,132.588) 1(55.7,64.718) 1(55.7,69.798) 1(106.201,124.206) 1(106.201,132.08) 1(111.281,124.206) 1(111.281,132.08) 1(150.093,33.604) 1(150.093,38.684) 1(150.093,76.581) 1(150.093,81.661) 1(150.093,111.963) 1(150.093,117.043) 1(155.173,33.604) 1(155.173,38.684) 1(155.173,76.581) 1(155.173,81.661) 1(155.173,111.963) 1(155.173,117.043)
  round 5.842 hole 3 mask+0.102: 1(14.753,9.576) 1(14.753,134.451) 1(154.613,9.576) 1(154.613,134.451)
  rect 0.8x1 smd paste+0 mask+0.102: 1(16.141,28.318)
  round 2.7 hole 1.8 mask+0.102: 1(16.785,52.646) 1(16.785,57.726) 1(16.785,73.076) 1(16.785,78.156) 1(25.675,131.496) 1(30.755,131.496) 1(50.395,67.258) 1(55.475,67.258) 1(152.633,33.604) 1(152.633,38.684) 1(152.633,76.581) 1(152.633,81.661) 1(152.633,111.963) 1(152.633,117.043)
  rect 0.83x0.63 smd paste+0 mask+0.102: 1(17.293,119.932) 1(17.293,122.232) 1(28.977,49.32) 1(28.977,51.62) 1(71.432,101.948) 1(71.432,104.249) 1(99.589,115.36) 1(99.589,117.66)
  oval 1.4x0.5 smd paste+0 mask+0.102: 1(19.267,87.554) 1(19.267,88.824) 1(19.267,90.094) 1(19.267,91.364) 1(25.222,120.066) 1(25.222,121.336) 1(25.222,122.606) 1(25.222,123.876) 1(39.193,101.905) 1(39.193,103.175) 1(39.193,104.445) 1(39.193,105.715) 1(40.857,89.078) 1(40.857,90.348) 1(40.857,91.618) 1(40.857,92.888)
  oval 1x0.5 smd paste+0 mask+0.102: 1(19.323,120.066) 1(19.323,121.336) 1(19.323,122.606) 1(19.323,123.876) 1(25.167,87.554) 1(25.167,88.824) 1(25.167,90.094) 1(25.167,91.364) 1(33.293,101.905) 1(33.293,103.175) 1(33.293,104.445) 1(33.293,105.715) 1(46.757,89.078) 1(46.757,90.348) 1(46.757,91.618) 1(46.757,92.888)
  rect 9x5 smd paste+0 mask+0.102: 1(19.325,102.978) 1(19.325,113.278)
  rect 5.632x5.7 smd paste+0 mask+0.102: 1(19.524,65.456) 1(98.772,131.242)
  round 0.5 hole 0.2 mask+0.102: 1(20.317,87.809) 1(20.317,88.909) 1(20.317,90.009) 1(20.317,91.109) 1(21.417,87.809) 1(21.417,88.909) 1(21.417,90.009) 1(21.417,91.109) 1(21.973,120.321) 1(21.973,121.421) 1(21.973,122.521) 1(21.973,123.621) 1(22.517,87.809) 1(22.517,88.909) 1(22.517,90.009) 1(22.517,91.109) 1(23.073,120.321) 1(23.073,121.421) 1(23.073,122.521) 1(23.073,123.621) 1(24.173,120.321) 1(24.173,121.421) 1(24.173,122.521) 1(24.173,123.621) 1(29.232,56.168) 1(29.232,57.268) 1(29.232,58.368) 1(30.332,56.168) 1(30.332,57.268) 1(30.332,58.368) 1(31.431,56.168) 1(31.431,57.268) 1(31.431,58.368) 1(32.532,56.168) 1(32.532,57.268) 1(32.532,58.368) 1(35.943,102.16) 1(35.943,103.26) 1(35.943,104.36) 1(35.943,105.46) 1(37.043,102.16) 1(37.043,103.26) 1(37.043,104.36) 1(37.043,105.46) 1(38.143,102.16) 1(38.143,103.26) 1(38.143,104.36) 1(38.143,105.46) 1(41.907,89.333) 1(41.907,90.433) 1(41.907,91.533) 1(41.907,92.633) 1(43.007,89.333) 1(43.007,90.433) 1(43.007,91.533) 1(43.007,92.633) 1(44.107,89.333) 1(44.107,90.433) 1(44.107,91.533) 1(44.107,92.633) 1(54.05,56.168) 1(54.05,57.268) 1(54.05,58.368) 1(55.149,56.168) 1(55.149,57.268) 1(55.149,58.368) 1(56.25,56.168) 1(56.25,57.268) 1(56.25,58.368) 1(57.35,56.168) 1(57.35,57.268) 1(57.35,58.368) 1(98.066,121.954) 1(98.066,123.054) 1(98.066,124.154) 1(99.166,121.954) 1(99.166,123.054) 1(99.166,124.154) 1(100.265,121.954) 1(100.265,123.054) 1(100.265,124.154) 1(101.366,121.954) 1(101.366,123.054) 1(101.366,124.154)
  rect 1.2x1 smd paste+0 mask+0.102: 1(22.342,28.168) 1(26.642,17.018)
  rect 1.7x2.5 smd paste+0 mask+0.102: 1(25.421,53.152) 1(25.421,57.152) 1(25.421,73.582) 1(25.421,77.582)
  rrect100% 1x1 smd paste+0 mask+0.102: 1(25.421,59.868) 1(25.421,81.204) 1(29.485,65.456) 1(34.057,39.802) 1(34.057,44.882) 1(38.121,123.876) 1(48.027,78.664) 1(84.129,84.328) 1(85.653,82.207) 1(90.301,57.569) 1(92.6,57.569) 1(103.598,24.968) 1(103.941,26.886) 1(106.839,128.803) 1(108.5,36.754) 1(108.729,41.694) 1(108.729,118.923) 1(108.868,76.962) 1(109.77,80.48) 1(111.574,119.088)
  rect 1.2x0.7 smd paste+0 mask+0.102: 1(26.642,18.568) 1(26.642,19.668) 1(26.642,20.768) 1(26.642,21.868) 1(26.642,22.968) 1(26.642,24.068) 1(26.642,25.168) 1(26.642,26.268) 1(26.642,27.218)
  rect 2.06x1.27 smd paste+0 mask+0.102: 1(27.961,120.597) 1(27.961,124.107) 1(31.101,120.597) 1(31.101,124.107) 1(57.383,92.987) 1(57.383,96.497) 1(60.177,92.987) 1(60.177,96.497) 1(62.971,92.987) 1(62.971,96.497)
  oval 0.5x1 smd paste+0 mask+0.102: 1(28.977,53.518) 1(30.247,53.518) 1(31.517,53.518) 1(32.787,53.518) 1(53.795,53.518) 1(55.065,53.518) 1(56.335,53.518) 1(57.605,53.518) 1(97.811,119.304) 1(99.081,119.304) 1(100.351,119.304) 1(101.621,119.304)
  oval 0.5x1.4 smd paste+0 mask+0.102: 1(28.977,59.418) 1(30.247,59.418) 1(31.517,59.418) 1(32.787,59.418) 1(53.795,59.418) 1(55.065,59.418) 1(56.335,59.418) 1(57.605,59.418) 1(97.811,125.204) 1(99.081,125.204) 1(100.351,125.204) 1(101.621,125.204)
  oct 1.408x1.408 / inner round 1.301 / far side oct 1.408x1.408 hole 0.9 rot 45 mask+0.102: 1(29.231,8.052) 1(81.555,69.52) 1(147.595,95.936) 1(149.373,15.164)
  rect 1.448x0.838 smd paste+0 mask+0.102: 1(29.485,34.803) 1(29.485,36.053) 1(29.485,37.302) 1(29.485,38.552) 1(29.485,39.802) 1(29.485,41.051) 1(29.485,42.301) 1(29.485,43.566)
  rect 1.27x2.06 smd paste+0 mask+0.102: 1(30.27,75.616) 1(30.27,78.773) 1(30.27,81.929) 1(30.27,85.086) 1(30.27,88.243) 1(30.27,91.4) 1(30.27,94.557) 1(30.27,97.714) 1(33.779,75.616) 1(33.779,78.773) 1(33.779,81.929) 1(33.779,85.086) 1(33.779,88.243) 1(33.779,91.4) 1(33.779,94.557) 1(33.779,97.714) 1(95.506,74.727) 1(95.506,85.09) 1(99.016,74.727) 1(99.016,85.09)
  rect 0.65x0.5 smd paste+0 mask+0.102: 1(32.533,23.108) 1(32.533,23.908) 1(32.533,24.708) 1(32.533,25.508) 1(33.783,23.108) 1(33.783,23.908) 1(33.783,24.708) 1(33.783,25.508) 1(46.893,40.38) 1(46.893,41.18) 1(46.893,41.98) 1(46.893,42.78) 1(48.144,40.38) 1(48.144,41.18) 1(48.144,41.98) 1(48.144,42.78)
  rect 3.4x2 smd paste+0 mask+0.102: 1(34.565,117.828) 1(34.565,123.828) 1(43.906,96.032) 1(43.906,102.032)
  rect 1x1.4 smd paste+0 mask+0.102: 1(35.986,20.428) 1(36.936,18.028) 1(37.886,20.428) 1(38.805,24.544) 1(39.755,22.344) 1(40.705,24.544) 1(42.26,14.115) 1(43.209,16.315) 1(44.159,14.115) 1(48.584,20.25) 1(49.524,24.544) 1(49.534,17.85) 1(50.474,22.344) 1(50.484,20.25) 1(51.424,24.544) 1(52.191,19.691) 1(53.141,17.291) 1(54.091,19.691) 1(59.811,19.691) 1(60.761,17.291) 1(61.711,19.691) 1(66.059,16.238) 1(67.009,14.038) 1(67.959,16.238) 1(73.324,55.126) 1(73.552,16.238) 1(74.274,52.926) 1(74.502,14.038) 1(75.224,55.126) 1(75.452,16.238) 1(81.045,16.238) 1(81.995,14.038) 1(82.945,16.238) 1(88.538,16.238) 1(89.488,14.038) 1(90.438,16.238) 1(94.067,122.522) 1(95.017,124.722) 1(95.967,122.522) 1(131.746,7.639) 1(131.746,15.119) 1(132.696,10.039) 1(132.696,12.719) 1(133.646,7.639) 1(133.646,15.119) 1(136.191,7.639) 1(136.191,15.119) 1(137.141,10.039) 1(137.141,12.719) 1(138.091,7.639) 1(138.091,15.119)
  rect 1.168x1.6 smd paste+0 mask+0.102: 1(36.089,39.802) 1(36.089,44.882) 1(37.613,39.802) 1(37.613,44.882) 1(39.137,39.802) 1(39.137,44.882)
  rect 0.55x1.5 smd far side paste+0 mask+0.102: 1(36.47,113.302) 1(36.47,118.702) 1(37.74,113.302) 1(37.74,118.702) 1(39.01,113.302) 1(39.01,118.702) 1(40.28,113.302) 1(40.28,118.702)
  rect 0.405x0.99 smd paste+0 mask+0.102: 1(36.622,109.487) 1(37.283,109.487) 1(37.943,109.487) 1(38.603,109.487)
  rect 0.405x0.76 smd paste+0 mask+0.102: 1(36.622,112.472) 1(37.283,112.472) 1(37.943,112.472) 1(38.603,112.472)
  rect 2.235x1.725 smd paste+0 mask+0.102: 1(37.613,111.479)
  rect 0.8x1.2 smd far side paste+0 mask+0.102: 1(38.48,121.082) 1(40.28,121.082) 1(69.589,30.759) 1(69.589,32.664) 1(69.589,35.052) 1(71.389,30.759) 1(71.389,32.664) 1(71.389,35.052) 1(76.905,119.705) 1(76.905,121.61) 1(78.705,119.705) 1(78.705,121.61) 1(86.955,119.558) 1(86.955,121.59) 1(88.754,119.558) 1(88.754,121.59) 1(88.783,97.968) 1(90.582,97.968) 1(97.289,97.46) 1(98.139,47.473) 1(98.215,36.043) 1(98.215,39.853) 1(98.215,43.663) 1(99.088,97.46) 1(99.939,47.473) 1(100.015,36.043) 1(100.015,39.853) 1(100.015,43.663) 1(108.045,38.075) 1(108.045,40.615) 1(108.045,43.155) 1(108.045,45.695) 1(108.073,24.562) 1(108.073,28.448) 1(108.073,30.404) 1(108.098,26.568) 1(109.845,38.075) 1(109.845,40.615) 1(109.845,43.155) 1(109.845,45.695) 1(109.873,24.562) 1(109.873,28.448) 1(109.873,30.404) 1(109.898,26.568) 1(116.404,12.446) 1(118.204,12.446) 1(119.553,12.446) 1(121.353,12.446) 1(123.971,125.882) 1(124.072,98.323) 1(124.098,24.968) 1(124.098,47.346) 1(124.098,58.496) 1(124.098,85.877) 1(125.77,125.882) 1(125.872,98.323) 1(125.897,24.968) 1(125.897,47.346) 1(125.897,58.496) 1(125.897,85.877) 1(144.166,53.721) 1(145.053,11.049) 1(145.966,53.721) 1(146.852,11.049) 1(150.26,57.508) 1(150.285,59.21) 1(152.059,57.508) 1(152.085,59.21)
  round 4 hole 4 mask+0.102: 1(39.137,133.274)
  oct 1.524x1.524 / inner round 1.408 / far side oct 1.524x1.524 hole 1.016 rot 135 mask+0.102: 1(39.958,8.136) 1(47.578,8.136) 1(53.141,8.136) 1(60.761,8.136)
  rect 1.2x1.2 smd paste+0 mask+0.102: 1(40.407,31.42) 1(40.407,33.452) 1(40.407,35.484) 1(42.507,31.42) 1(42.507,33.452) 1(42.507,35.484) 1(66.027,107.366) 1(68.042,82.263) 1(68.127,107.366) 1(70.142,82.263) 1(87.837,76.75) 1(87.837,78.85) 1(87.837,84.015) 1(87.837,86.115) 1(106.151,112.171) 1(106.151,114.271) 1(140.282,7.671) 1(140.282,10.211) 1(140.282,12.751) 1(140.282,15.291) 1(142.382,7.671) 1(142.382,10.211) 1(142.382,12.751) 1(142.382,15.291)
  oval 4.5x2.25 hole 1.5 mask+0.102: 1(41.931,63.742) 1(41.931,69.442) 1(41.931,78.742) 1(41.931,84.442) 1(64.029,113.018) 1(64.029,118.718) 1(64.029,128.018) 1(64.029,133.718)
  oct 1.524x1.524 / inner round 1.408 / far side oct 1.524x1.524 hole 1.016 rot 45 mask+0.102: 1(42.439,38.532) 1(42.439,46.152) 1(106.151,35.535) 1(106.151,48.235)
  oct 1.524x1.524 hole 1.016 rot 45 mask+0.102: 1(42.439,41.072) 1(42.439,43.612) 1(106.151,38.075) 1(106.151,40.615) 1(106.151,43.155) 1(106.151,45.695)
  rect 1.2x0.8 smd far side paste+0 mask+0.102: 1(42.439,116.902) 1(42.439,118.702) 1(50.321,8.625) 1(50.321,10.425) 1(54.03,22.341) 1(54.03,24.141) 1(54.157,12.283) 1(54.157,14.083) 1(55.859,22.341) 1(55.859,24.141) 1(55.909,17.591) 1(55.909,19.391) 1(57.992,17.591) 1(57.992,19.391) 1(57.992,21.503) 1(57.992,23.303) 1(59.745,12.283) 1(59.745,14.083) 1(60.761,21.503) 1(60.761,23.303) 1(63.123,10.911) 1(63.123,12.711) 1(63.301,6.847) 1(63.301,8.647) 1(64.266,18.531) 1(64.266,20.331) 1(64.901,10.911) 1(64.901,12.711) 1(65.917,37.683) 1(65.917,39.483) 1(66.171,18.531) 1(66.171,20.331) 1(66.933,10.911) 1(66.933,12.711) 1(68.076,18.531) 1(68.076,20.331) 1(68.254,37.683) 1(68.254,39.483) 1(68.711,10.911) 1(68.711,12.711) 1(69.981,18.531) 1(69.981,20.331) 1(70.743,10.911) 1(70.743,12.711) 1(71.886,18.531) 1(71.886,20.331) 1(72.521,10.911) 1(72.521,12.711) 1(73.791,18.531) 1(73.791,20.331) 1(74.553,10.911) 1(74.553,12.711) 1(75.696,18.531) 1(75.696,20.331) 1(76.331,10.911) 1(76.331,12.711) 1(77.601,18.531) 1(77.601,20.331) 1(78.363,10.911) 1(78.363,12.711) 1(79.506,18.531) 1(79.506,20.331) 1(80.141,10.911) 1(80.141,12.711) 1(81.411,18.531) 1(81.411,20.331) 1(82.173,10.911) 1(82.173,12.711) 1(83.316,18.531) 1(83.316,20.331) 1(83.951,10.911) 1(83.951,12.711) 1(85.221,18.531) 1(85.221,20.331) 1(85.983,10.911) 1(85.983,12.711) 1(87.126,18.531) 1(87.126,20.331) 1(87.761,10.911) 1(87.761,12.711) 1(89.031,18.531) 1(89.031,20.331) 1(89.793,10.911) 1(89.793,12.711) 1(90.936,18.531) 1(90.936,20.331) 1(91.52,62.676) 1(91.52,64.476) 1(91.571,10.911) 1(91.571,12.711) 1(92.841,18.531) 1(92.841,20.331) 1(93.349,62.702) 1(93.349,64.502) 1(95.127,62.702) 1(95.127,64.502) 1(96.93,62.702) 1(96.93,64.502) 1(123.12,14.569) 1(123.12,16.369) 1(138.995,57.698) 1(138.995,59.498) 1(140.697,57.647) 1(140.697,59.447)
  oct 1.524x1.524 hole 1.016 rot 135 mask+0.102: 1(42.498,8.136) 1(45.038,8.136) 1(55.681,8.136) 1(58.221,8.136)
  rect 0.9x0.8 smd paste+0 mask+0.102: 1(43.725,52.06) 1(43.725,53.96) 1(45.825,53.01)
  rect 1.2x0.6 smd paste+0 mask+0.102: 1(43.927,56.328) 1(43.927,57.278) 1(43.927,58.228) 1(46.539,56.328) 1(46.539,58.228)
  round 2.54 hole 1.016 mask+0.102: 1(45.487,107.874) 1(127.54,22.403) 1(127.54,50.241) 1(127.54,61.849) 1(127.54,88.697) 1(127.54,100.787) 1(127.54,128.067)
  oct 2.54x2.54 / inner round 2.347 / far side oct 2.54x2.54 hole 1.016 rot 135 mask+0.102: 1(45.487,112.954)
  rrect100% 1.27x1.27 smd paste+0 mask+0.102: 1(47.519,46.406) 1(47.519,48.438)
  rect 1x1.4 smd far side paste+0 mask+0.102: 1(52.191,17.391) 1(53.141,19.591) 1(54.091,17.391) 1(56.001,13.8) 1(56.951,11.6) 1(57.901,13.8) 1(59.811,17.391) 1(60.761,19.591) 1(61.711,17.391) 1(63.841,16.729) 1(64.791,14.529) 1(65.741,16.729) 1(67.761,16.721) 1(68.711,14.521) 1(69.661,16.721) 1(71.571,16.721) 1(72.521,14.521) 1(73.471,16.721) 1(75.381,16.721) 1(76.331,14.521) 1(76.905,117.63) 1(77.281,16.721) 1(77.855,115.43) 1(78.805,117.63) 1(79.191,16.721) 1(80.141,14.521) 1(81.091,16.721) 1(83.001,16.721) 1(83.951,14.521) 1(84.901,16.721) 1(86.811,16.721) 1(86.955,117.61) 1(87.761,14.521) 1(87.905,115.41) 1(88.711,16.721) 1(88.855,117.61) 1(90.621,16.721) 1(91.571,14.521) 1(92.521,16.721)
  rrect100% 1x1 smd paste+0: 1(55.786,130.625) 1(83.9,94.64) 1(95.953,53.95) 1(149.623,133.401)
  rrect100% 1x1 smd far side paste+0: 1(55.786,130.625) 1(83.9,94.64) 1(97.303,13.513) 1(149.623,133.401)
  oct 1.93x1.93 / inner round 1.784 / far side oct 1.93x1.93 hole 1.016 rot 45 mask+0.102: 1(57.425,30.404) 1(57.425,40.564) 1(105.871,12.649) 1(112.958,23.8) 1(127.616,14.554) 1(149.305,8.509) 1(149.305,11.049)
  oct 1.93x1.93 hole 1.016 rot 45 mask+0.102: 1(57.425,32.944) 1(57.425,35.484) 1(57.425,38.024) 1(105.871,15.189) 1(105.871,17.729) 1(105.871,20.269) 1(105.871,22.809) 1(105.871,25.349) 1(105.871,27.889) 1(105.871,30.429) 1(112.958,26.34) 1(127.616,12.014)
  rect 1.95x1.95 / inner round 1.802 / far side rect 1.95x1.95 hole 1.3 mask+0.102: 1(66.061,49.788)
  round 1.95 hole 1.3 mask+0.102: 1(66.061,59.788)
  round 1.108 hole 0.6 mask+0.102: 1(66.425,30.556) 1(66.425,31.826) 1(66.425,33.096) 1(66.425,34.366) 1(66.425,35.636) 1(67.695,30.556) 1(67.695,31.826) 1(67.695,33.096) 1(67.695,34.366) 1(67.695,35.636)
  rect 0.805x0.3 smd paste+0 mask+0.102: 1(67.674,95.655) 1(67.674,96.155) 1(67.674,96.655) 1(67.674,97.155) 1(67.674,97.655) 1(67.674,98.155) 1(67.674,98.655) 1(74.579,95.655) 1(74.579,96.155) 1(74.579,96.655) 1(74.579,97.155) 1(74.579,97.655) 1(74.579,98.155) 1(74.579,98.655)
  rect 0.3x0.805 smd paste+0 mask+0.102: 1(68.377,94.703) 1(68.377,99.607) 1(68.877,94.703) 1(68.877,99.607) 1(69.377,94.703) 1(69.377,99.607) 1(69.877,94.703) 1(69.877,99.607) 1(70.377,94.703) 1(70.377,99.607) 1(70.877,94.703) 1(70.877,99.607) 1(71.377,94.703) 1(71.377,99.607) 1(71.877,94.703) 1(71.877,99.607) 1(72.377,94.703) 1(72.377,99.607) 1(72.877,94.703) 1(72.877,99.607) 1(73.377,94.703) 1(73.377,99.607) 1(73.877,94.703) 1(73.877,99.607)
  oct 1.93x1.93 hole 1.016 rot 135 mask+0.102: 1(69.346,8.636) 1(71.886,8.636) 1(74.426,8.636) 1(76.966,8.636) 1(79.506,8.636) 1(80.085,59.758) 1(82.046,8.636) 1(82.625,59.758) 1(84.586,8.636) 1(85.165,59.758) 1(87.126,8.636) 1(87.705,59.758) 1(90.245,59.758) 1(92.785,59.758) 1(95.325,59.758) 1(104.195,53.645) 1(106.735,53.645)
  rect 1.8x1.3 smd paste+0 mask+0.102: 1(70.648,20.314) 1(70.648,22.714) 1(74.648,20.314) 1(74.648,22.714)
  rect 5.25x3.25 smd paste+0 mask+0.102: 1(71.127,97.155)
  rect 1.8x1 smd paste+0 mask+0.102: 1(72.597,42.362) 1(72.597,44.862)
  rect 1.219x0.279 smd paste+0 mask+0.102: 1(75.417,27.648) 1(75.417,28.148) 1(75.417,28.648) 1(75.417,29.148) 1(75.417,29.648) 1(75.417,30.148) 1(75.417,30.648) 1(75.417,31.148) 1(75.417,31.648) 1(75.417,32.148) 1(75.417,32.648) 1(75.417,33.148) 1(75.417,33.648) 1(75.417,34.148) 1(75.417,34.648) 1(75.417,35.148) 1(75.417,35.648) 1(75.417,36.148) 1(75.417,36.648) 1(75.417,37.148) 1(75.417,37.648) 1(75.417,38.148) 1(75.417,38.648) 1(75.417,39.148) 1(75.417,39.648) 1(75.417,40.148) 1(75.417,40.648) 1(75.417,41.148) 1(75.417,41.648) 1(75.417,42.148) 1(75.417,42.648) 1(75.417,43.148) 1(75.417,43.648) 1(75.417,44.148) 1(75.417,44.648) 1(75.417,45.148) 1(96.905,27.648) 1(96.905,28.148) 1(96.905,28.648) 1(96.905,29.148) 1(96.905,29.648) 1(96.905,30.148) 1(96.905,30.648) 1(96.905,31.148) 1(96.905,31.648) 1(96.905,32.148) 1(96.905,32.648) 1(96.905,33.148) 1(96.905,33.648) 1(96.905,34.148) 1(96.905,34.648) 1(96.905,35.148) 1(96.905,35.648) 1(96.905,36.148) 1(96.905,36.648) 1(96.905,37.148) 1(96.905,37.648) 1(96.905,38.148) 1(96.905,38.648) 1(96.905,39.148) 1(96.905,39.648) 1(96.905,40.148) 1(96.905,40.648) 1(96.905,41.148) 1(96.905,41.648) 1(96.905,42.148) 1(96.905,42.648) 1(96.905,43.148) 1(96.905,43.648) 1(96.905,44.148) 1(96.905,44.648) 1(96.905,45.148)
